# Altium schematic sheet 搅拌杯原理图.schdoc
size 430 x 290 mm
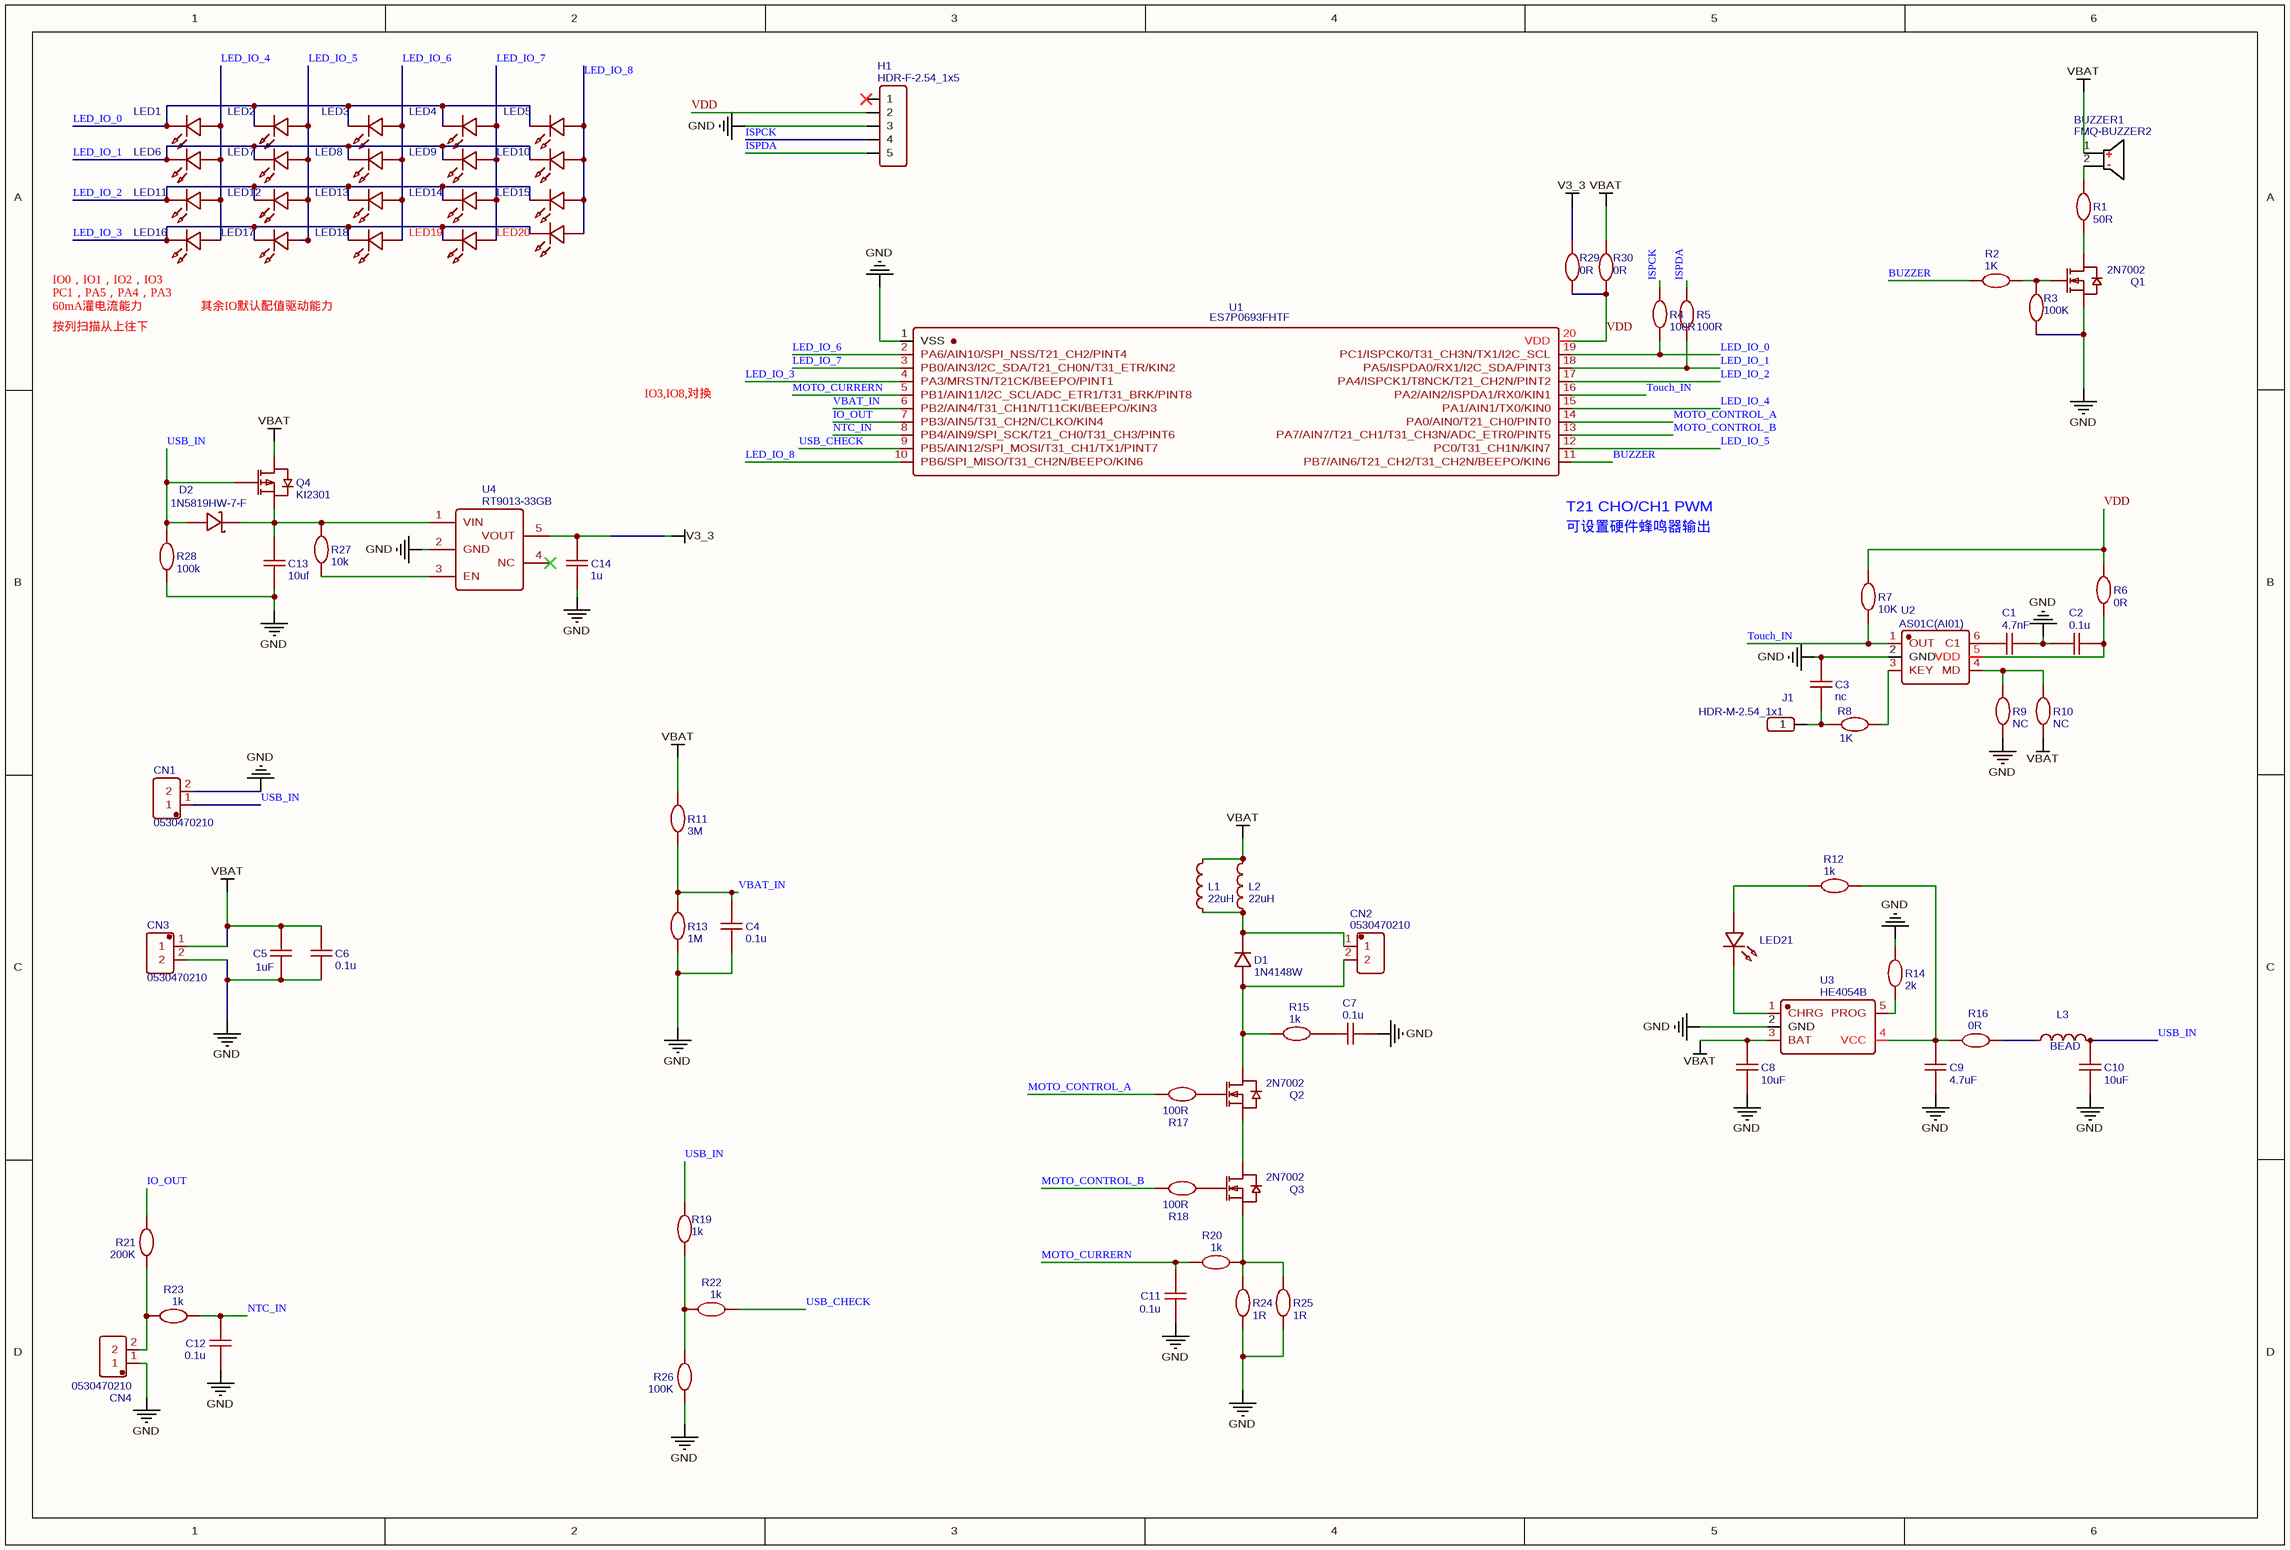
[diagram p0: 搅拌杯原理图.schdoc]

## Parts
BUZZER1  FMQ-BUZZER2  [BUZ-TH_BD12.0-P7.60-D0.6-FD]
C1  4.7nF  [C0603]
C2  0.1u  [C0603]
C3  nc  [C0603]
C4  0.1u  [C0603]
C5  1uF  [C0603]
C6  0.1u  [C0603]
C7  0.1u  [C0603]
C8  10uF  [C0603]
C9  4.7uF  [C0603]
C10  10uF  [C0603]
C11  0.1u  [C0603]
C12  0.1u  [C0603]
C13  10uf  [C0603]
C14  1u  [C0603]
CN1  0530470210  [CONN-TH_0530470210]
CN2  0530470210  [CONN-TH_0530470210]
CN3  0530470210  [CONN-TH_0530470210]
CN4  0530470210  [CONN-TH_0530470210]
D1  1N4148W  [SOD-123FL_L2.6-W1.6-LS3.4-RD]
D2  1N5819HW-7-F  [SOD-123_L2.8-W1.8-LS3.7-FD]
H1  HDR-F-2.54_1x5  [1.27mm_5PIN]
J1  HDR-M-2.54_1x1  [HDR-M-2.54_1X1]
L1  22uH  [L0603]
L2  22uH  [L0603]
L3  BEAD  [L0603]
LED1  LED-0603_W  [LED0603-FD_WHITE]  (value not drawn)
LED2  LED-0603_W  [LED0603-FD_WHITE]  (value not drawn)
LED3  LED-0603_W  [LED0603-FD_WHITE]  (value not drawn)
LED4  LED-0603_W  [LED0603-FD_WHITE]  (value not drawn)
LED5  LED-0603_W  [LED0603-FD_WHITE]  (value not drawn)
LED6  LED-0603_W  [LED0603-FD_WHITE]  (value not drawn)
LED7  LED-0603_W  [LED0603-FD_WHITE]  (value not drawn)
LED8  LED-0603_W  [LED0603-FD_WHITE]  (value not drawn)
LED9  LED-0603_W  [LED0603-FD_WHITE]  (value not drawn)
LED10  LED-0603_W  [LED0603-FD_WHITE]  (value not drawn)
LED11  LED-0603_W  [LED0603-FD_WHITE]  (value not drawn)
LED12  LED-0603_W  [LED0603-FD_WHITE]  (value not drawn)
LED13  LED-0603_W  [LED0603-FD_WHITE]  (value not drawn)
LED14  LED-0603_W  [LED0603-FD_WHITE]  (value not drawn)
LED15  LED-0603_W  [LED0603-FD_WHITE]  (value not drawn)
LED16  LED-0603_W  [LED0603-FD_WHITE]  (value not drawn)
LED17  LED-0603_W  [LED0603-FD_WHITE]  (value not drawn)
LED18  LED-0603_W  [LED0603-FD_WHITE]  (value not drawn)
LED19  LED-0603_W  [LED0603-FD_WHITE]  (value not drawn)
LED20  LED-0603_W  [LED0603-FD_WHITE]  (value not drawn)
LED21  LED-0603_W  [LED0603-FD_WHITE]  (value not drawn)
Q1  2N7002  [SOT-23_L2.9-W1.3-P0.95-LS2.4-BR]
Q2  2N7002  [SOT-23_L2.9-W1.3-P0.95-LS2.4-BR]
Q3  2N7002  [SOT-23_L2.9-W1.3-P0.95-LS2.4-BR]
Q4  KI2301  [SOT-23-3_L2.9-W1.3-P1.90-LS2.4-BR]
R1  50R  [R0603]
R2  1K  [R0603]
R3  100K  [R0603]
R4  100R  [R0603]
R5  100R  [R0603]
R6  0R  [R0603]
R7  10K  [R0603]
R8  1K  [R0603]
R9  NC  [R0603]
R10  NC  [R0603]
R11  3M  [R0603]
R12  1k  [R0603]
R13  1M  [R0603]
R14  2k  [R0603]
R15  1k  [R0603]
R16  0R  [R0603]
R17  100R  [R0603]
R18  100R  [R0603]
R19  1k  [R0603]
R20  1k  [R0603]
R21  200K  [R0603]
R22  1k  [R0603]
R23  1k  [R0603]
R24  1R  [R1206]
R25  1R  [R1206]
R26  100K  [R0603]
R27  10k  [R0603]
R28  100k  [C0603]
R29  0R  [R0603]
R30  0R  [R0603]
U1  ES7P0693FHTF  [TSOP20]  (value not drawn)
U2  AS01C(AI01)  [SOT-23-6_L2.9-W1.6-P0.95-LS2.8-BL]
U3  HE4054B  [SOT-23-5_L3.0-W1.7-P0.95-LS2.8-BR]
U4  RT9013-33GB  [SOT-23-5_L3.0-W1.7-P0.95-LS2.8-BR]

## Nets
GND: C1.2 C2.1 C3.2 C4.1 C5.2 C6.2 C7.1 C8.1 C9.1 C10.1 C11.1 C12.2 C13.1 C14.1 CN1.2 CN3.2 CN4.1 H1.3 Q1.2(S) R3.2 R9.1 R13.1 R14.2 R24.1 R25.1 R26.2 R28.1 U1.1(VSS) U2.2(GND) U3.2(GND) U4.2(GND)
V3_3: C14.2 R29.2 U4.5(VOUT)
VBAT: BUZZER1.1 C5.1 C6.1 C8.2 CN3.1 L1.2 L2.2 Q4.3(D) R10.1 R11.2 R30.2 U3.3(BAT)
BUZZER: R2.2 U1.11(PB7/AIN6/T21_CH2/T31_CH2N/BEEPO/KIN6)
IO_OUT: R21.1 U1.7(PB3/AIN5/T31_CH2N/CLKO/KIN4)
ISPCK: H1.4 R4.1
ISPDA: H1.5 R5.1
LED_IO_0: LED1.2 LED2.2 LED3.2 LED4.2 LED5.2 R4.2 U1.19(PC1/ISPCK0/T31_CH3N/TX1/I2C_SCL)
LED_IO_1: LED6.2 LED7.2 LED8.2 LED9.2 LED10.2 R5.2 U1.18(PA5/ISPDA0/RX1/I2C_SDA/PINT3)
LED_IO_2: LED11.2 LED12.2 LED13.2 LED14.2 LED15.2 U1.17(PA4/ISPCK1/T8NCK/T21_CH2N/PINT2)
LED_IO_3: LED16.2 LED17.2 LED18.2 LED19.2 LED20.2 U1.4(PA3/MRSTN/T21CK/BEEPO/PINT1)
LED_IO_4: LED1.1 LED6.1 LED11.1 LED16.1 U1.15(PA1/AIN1/TX0/KIN0)
LED_IO_5: LED2.1 LED7.1 LED12.1 LED17.1 U1.12(PC0/T31_CH1N/KIN7)
LED_IO_6: LED3.1 LED8.1 LED13.1 LED18.1 U1.2(PA6/AIN10/SPI_NSS/T21_CH2/PINT4)
LED_IO_7: LED4.1 LED9.1 LED14.1 LED19.1 U1.3(PB0/AIN3/I2C_SDA/T21_CH0N/T31_ETR/KIN2)
LED_IO_8: LED5.1 LED10.1 LED15.1 LED20.1 U1.10(PB6/SPI_MISO/T31_CH2N/BEEPO/KIN6)
MOTO_CONTROL_A: R17.1 U1.14(PA0/AIN0/T21_CH0/PINT0)
MOTO_CONTROL_B: R18.1 U1.13(PA7/AIN7/T21_CH1/T31_CH3N/ADC_ETR0/PINT5)
MOTO_CURRERN: C11.2 R20.2 U1.5(PB1/AIN11/I2C_SCL/ADC_ETR1/T31_BRK/PINT8)
NTC_IN: C12.1 R23.2 U1.8(PB4/AIN9/SPI_SCK/T21_CH0/T31_CH3/PINT6)
Touch_IN: R7.1 U1.16(PA2/AIN2/ISPDA1/RX0/KIN1) U2.1(OUT)
USB_CHECK: R22.2 U1.9(PB5/AIN12/SPI_MOSI/T31_CH1/TX1/PINT7)
USB_IN: C10.2 CN1.1 D2.1(A) L3.2 Q4.1(G) R19.2 R28.2
VBAT_IN: C4.2 R11.1 R13.2 U1.6(PB2/AIN4/T31_CH1N/T11CKI/BEEPO/KIN3)
VDD: H1.2 R6.2 R7.2 R29.1 R30.1 U1.20(VDD)
NetBUZZER1_2: BUZZER1.2 R1.1
NetC1_1: C1.1 U2.6(C1)
NetC2_2: C2.2 R6.1 U2.5(VDD)
NetC3_1: C3.1 J1.1 R8.2
NetC7_2: C7.2 R15.1
NetC9_2: C9.2 R12.1 R16.1 U3.4(VCC)
NetC13_2: C13.2 D2.2(K) Q4.2(S) R27.2 U4.1(VIN)
NetCN2_1: CN2.1 D1.1 L1.1 L2.1
NetCN2_2: CN2.2 D1.2 Q2.3(D) R15.2
NetCN4_2: CN4.2 R21.2 R23.1
NetL3_1: L3.1 R16.2
NetLED21_1: LED21.1 R12.2
NetLED21_2: LED21.2 U3.1(CHRG)
NetQ1_1: Q1.1(G) R2.1 R3.1
NetQ1_3: Q1.3(D) R1.2
NetQ2_1: Q2.1(G) R17.2
NetQ2_2: Q2.2(S) Q3.3(D)
NetQ3_1: Q3.1(G) R18.2
NetQ3_2: Q3.2(S) R20.1 R24.2 R25.2
NetR8_1: R8.1 U2.3(KEY)
NetR9_2: R9.2 R10.2 U2.4(MD)
NetR14_1: R14.1 U3.5(PROG)
NetR19_1: R19.1 R22.1 R26.1
NetR27_1: R27.1 U4.3(EN)

Not connected (* = marked no-connect by the designer): H1 1*; U4 4(NC)*

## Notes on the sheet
- IO0，IO1，IO2，IO3
- PC1，PA5，PA4，PA3
- 60mA灌电流能力
- 按列扫描从上往下
- 其余IO默认配值驱动能力
- IO3,IO8,对换
- 可设置硬件蜂鸣器输出
- (near U1) T21 CHO/CH1 PWM

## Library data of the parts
BUZZER1 = FMQ-BUZZER2: Contributor: LCSC
C1 = 4.7nF: nameAlias: Value(F); Contributor: LCEDA_Lib
C2 C4 C6 C7 C11 C12 = 0.1u: nameAlias: Value(F); Contributor: LCEDA_Lib
C3 = nc: nameAlias: Value(F); Contributor: LCEDA_Lib
C5 = 1uF: nameAlias: Value(F); Contributor: LCEDA_Lib
C8 C10 = 10uF: nameAlias: Value(F); Contributor: LCEDA_Lib
C9 = 4.7uF: nameAlias: Value(F); Contributor: LCEDA_Lib
C13 = 10uf: BOM_Manufacturer Part: JMK105CBJ106MV-F; BOM_Manufacturer: TAIYO YUDEN; nameAlias: Value(F); Contributor: LCEDA_Lib
C14 = 1u: nameAlias: Value(F); Contributor: LCEDA_Lib
CN1-CN4 = 0530470210: BOM_Manufacturer: MOLEX; Contributor: LCSC
D1 = 1N4148W: BOM_Manufacturer: Tak Cheong; Contributor: LCEDA_Lib
D2 = 1N5819HW-7-F: BOM_Manufacturer: DIODES
H1 = HDR-F-2.54_1x5: Contributor: LCEDA_Lib
J1 = HDR-M-2.54_1x1: Contributor: LCEDA_Lib
L1-L3 = 22uH: nameAlias: Value(H); Contributor: LCEDA_Lib
LED1-LED21 = LED-0603_W: BOM_Manufacturer: EVERLIGHT(台湾亿光); BOM_Manufacturer Part: 17-21SURC/S530-A3/TR8; Contributor: LCEDA_Lib
Q1-Q3 = 2N7002: BOM_Manufacturer: Nexperia; BOM_Manufacturer Part: 2N7002,215; BOM_Paste Type: expand; Contributor: LCEDA_Lib
Q4 = KI2301: BOM_Manufacturer: LGE; Contributor: LCSC
R1 R4 R5 R17 R18 = 100R: nameAlias: Value(Ω); Contributor: LCEDA_Lib
R2 R3 R8 = 1K: nameAlias: Value(Ω); Contributor: LCEDA_Lib
R6 R7 R9 R10 R16 R29 R30 = NC: nameAlias: Value(Ω); Contributor: LCEDA_Lib
R11 = 430k: nameAlias: Value(Ω); Contributor: LCEDA_Lib
R12 R14 R15 R19 R20 R22 R23 = 1k: nameAlias: Value(Ω); Contributor: LCEDA_Lib
R13 = 430K: nameAlias: Value(Ω); Contributor: LCEDA_Lib
R21 R26 = 33K: nameAlias: Value(Ω); Contributor: LCEDA_Lib
R24 R25 = 1R: nameAlias: Value(Ω); Contributor: LCEDA_Lib
R27 = 10k: nameAlias: Value(Ω); Contributor: LCEDA_Lib
R28 = 100k: nameAlias: Value(Ω); Contributor: LCEDA_Lib
U1 = ES7P0693FHTF: Contributor: zime_zl
U2 = AS01C(AI01): BOM_Manufacturer: Sam&wing; Contributor: LCSC
U3 = HE4054B: BOM_Manufacturer: HEERMICR; Contributor: LCSC
U4 = RT9013-33GB: BOM_Manufacturer: RICHTEK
